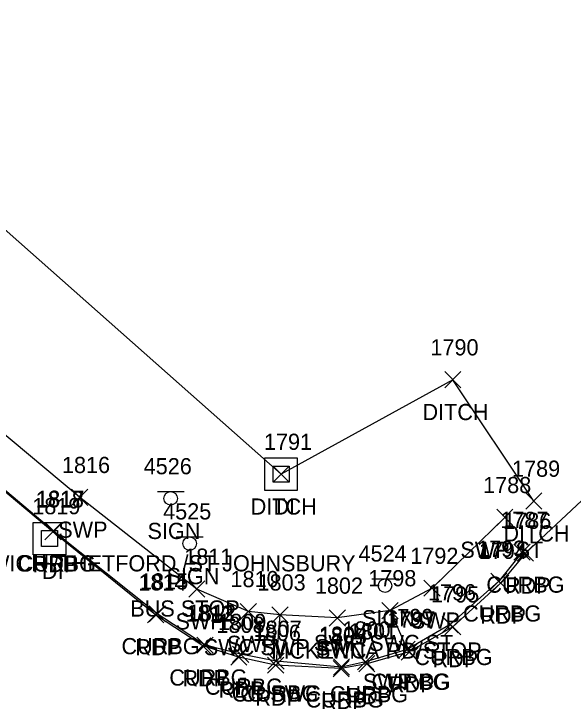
# Model space of a CAD drawing. Extents: x 1690689 to 1696275, y 438760 to 444007.
# Drawn here: x 1691916.7 to 1691985.8, y 439244.2 to 439330.1 of the extents above; entities that cross this region are included whole.
import ezdxf

# ---------------------------------------------------------------- set-up
doc = ezdxf.new("R2010")
doc.units = 0
for name, color, linetype in [('D_A', 7, 'Continuous'), ('D_I', 7, 'Continuous'), ('D_TIC', 7, 'Continuous'), ('DD', 7, 'Continuous'), ('DS', 7, 'Continuous'), ('P_A', 7, 'Continuous'), ('P_I', 7, 'Continuous'), ('P_TIC', 7, 'Continuous'), ('PET', 7, 'Continuous'), ('R_A', 7, 'Continuous'), ('R_I', 7, 'Continuous'), ('R_TIC', 7, 'Continuous'), ('RC', 7, 'Continuous'), ('RSW', 7, 'Continuous'), ('S_A', 7, 'Continuous'), ('S_C', 7, 'Continuous'), ('S_I', 7, 'Continuous'), ('SSGN', 7, 'Continuous')]:
    doc.layers.add(name, color=color, linetype=linetype)

msp = doc.modelspace()

# ---------------------------------------------------------------- linework, layer by layer
at = {"layer": 'D_TIC'}
for points in [[(1691969.983, 439283.898), (1691971.983, 439285.898)], [(1691971.983, 439283.898), (1691969.983, 439285.898)], [(1691948.75, 439272.221), (1691950.75, 439274.221)], [(1691950.75, 439272.221), (1691948.75, 439274.221)], [(1691979.993, 439268.897), (1691981.993, 439270.897)], [(1691981.993, 439268.897), (1691979.993, 439270.897)]]:
    msp.add_lwpolyline(points, dxfattribs=at)
at = {"layer": 'DD'}
msp.add_lwpolyline([(1691980.993, 439269.897), (1691970.983, 439284.898), (1691949.75, 439273.221), (1691908.637, 439309.602), (1691878.878, 439338.951), (1691850.288, 439370.611), (1691847.882, 439389.439)], dxfattribs=at)
at = {"layer": 'DS'}
for p, q in [((1691947.745, 439275.22), (1691951.745, 439275.22)), ((1691947.745, 439271.22), (1691947.745, 439275.22)), ((1691951.745, 439275.22), (1691951.745, 439271.22)), ((1691948.745, 439272.22), (1691948.745, 439274.22)), ((1691948.745, 439274.22), (1691950.745, 439274.22)), ((1691950.745, 439274.22), (1691950.745, 439272.22)), ((1691949.75, 439273.221), (1691949.75, 439273.221)), ((1691949.75, 439273.221), (1691949.75, 439273.221)), ((1691950.745, 439272.22), (1691948.745, 439272.22)), ((1691951.745, 439271.22), (1691947.745, 439271.22)), ((1691919.112, 439267.262), (1691923.112, 439267.262)), ((1691919.112, 439263.262), (1691919.112, 439267.262)), ((1691923.112, 439267.262), (1691923.112, 439263.262)), ((1691920.112, 439264.262), (1691920.112, 439266.262)), ((1691920.112, 439266.262), (1691922.112, 439266.262)), ((1691922.112, 439266.262), (1691922.112, 439264.262)), ((1691921.117, 439265.263), (1691921.117, 439265.263)), ((1691921.117, 439265.263), (1691921.117, 439265.263)), ((1691922.112, 439264.262), (1691920.112, 439264.262)), ((1691923.112, 439263.262), (1691919.112, 439263.262))]:
    msp.add_line(p, q, dxfattribs=at)
at = {"layer": 'P_TIC'}
for points in [[(1691920.536, 439265.097), (1691922.536, 439267.097)], [(1691922.536, 439265.097), (1691920.536, 439267.097)], [(1691978.943, 439262.456), (1691980.943, 439264.456)], [(1691980.943, 439262.456), (1691978.943, 439264.456)], [(1691975.877, 439258.745), (1691977.877, 439260.745)], [(1691977.877, 439258.745), (1691975.877, 439260.745)], [(1691933.231, 439254.841), (1691935.231, 439256.841)], [(1691935.231, 439254.841), (1691933.231, 439256.841)], [(1691969.973, 439253.359), (1691971.973, 439255.359)], [(1691971.973, 439253.359), (1691969.973, 439255.359)], [(1691939.058, 439250.999), (1691941.058, 439252.999)], [(1691941.058, 439250.999), (1691939.058, 439252.999)], [(1691964.575, 439250.247), (1691966.575, 439252.247)], [(1691966.575, 439250.247), (1691964.575, 439252.247)], [(1691943.521, 439249.599), (1691945.521, 439251.599)], [(1691945.521, 439249.599), (1691943.521, 439251.599)], [(1691948.065, 439248.613), (1691950.065, 439250.613)], [(1691950.065, 439248.613), (1691948.065, 439250.613)], [(1691956.174, 439248.184), (1691958.174, 439250.184)], [(1691958.174, 439248.184), (1691956.174, 439250.184)], [(1691959.334, 439248.793), (1691961.334, 439250.793)], [(1691961.334, 439248.793), (1691959.334, 439250.793)]]:
    msp.add_lwpolyline(points, dxfattribs=at)
at = {"layer": 'PET'}
msp.add_lwpolyline([(1691992.617, 439275.273), (1691979.943, 439263.456), (1691976.877, 439259.745), (1691970.973, 439254.359), (1691965.575, 439251.247), (1691960.334, 439249.793), (1691957.174, 439249.184), (1691949.065, 439249.613), (1691944.521, 439250.599), (1691940.058, 439251.999), (1691934.231, 439255.841), (1691921.536, 439266.097), (1691889.347, 439293.069), (1691851.08, 439328.772), (1691838.858, 439341.344)], dxfattribs=at)
at = {"layer": 'R_TIC'}
for points in [[(1691923.832, 439269.357), (1691925.832, 439271.357)], [(1691925.832, 439269.357), (1691923.832, 439271.357)], [(1691976.41, 439266.877), (1691978.41, 439268.877)], [(1691978.41, 439266.877), (1691976.41, 439268.877)], [(1691920.599, 439265.187), (1691922.599, 439267.187)], [(1691922.599, 439265.187), (1691920.599, 439267.187)], [(1691978.534, 439262.57), (1691980.534, 439264.57)], [(1691980.534, 439262.57), (1691978.534, 439264.57)], [(1691975.66, 439259.001), (1691977.66, 439261.001)], [(1691977.66, 439259.001), (1691975.66, 439261.001)], [(1691938.327, 439258.026), (1691940.327, 439260.026)], [(1691940.327, 439258.026), (1691938.327, 439260.026)], [(1691967.406, 439258.126), (1691969.406, 439260.126)], [(1691969.406, 439258.126), (1691967.406, 439260.126)], [(1691933.433, 439254.965), (1691935.433, 439256.965)], [(1691935.433, 439254.965), (1691933.433, 439256.965)], [(1691944.698, 439255.254), (1691946.698, 439257.254)], [(1691946.698, 439255.254), (1691944.698, 439257.254)], [(1691948.598, 439254.837), (1691950.598, 439256.837)], [(1691950.598, 439254.837), (1691948.598, 439256.837)], [(1691948.598, 439254.837), (1691950.598, 439256.837)], [(1691950.598, 439254.837), (1691948.598, 439256.837)], [(1691962.208, 439255.36), (1691964.208, 439257.36)], [(1691964.208, 439255.36), (1691962.208, 439257.36)], [(1691962.208, 439255.36), (1691964.208, 439257.36)], [(1691964.208, 439255.36), (1691962.208, 439257.36)], [(1691955.688, 439254.444), (1691957.688, 439256.444)], [(1691957.688, 439254.444), (1691955.688, 439256.444)], [(1691969.639, 439253.621), (1691971.639, 439255.621)], [(1691971.639, 439253.621), (1691969.639, 439255.621)], [(1691939.345, 439251.087), (1691941.345, 439253.087)], [(1691941.345, 439251.087), (1691939.345, 439253.087)], [(1691964.326, 439250.566), (1691966.326, 439252.566)], [(1691966.326, 439250.566), (1691964.326, 439252.566)], [(1691964.326, 439250.566), (1691966.326, 439252.566)], [(1691966.326, 439250.566), (1691964.326, 439252.566)], [(1691943.741, 439249.958), (1691945.741, 439251.958)], [(1691945.741, 439249.958), (1691943.741, 439251.958)], [(1691948.113, 439249.109), (1691950.113, 439251.109)], [(1691950.113, 439249.109), (1691948.113, 439251.109)], [(1691948.113, 439249.109), (1691950.113, 439251.109)], [(1691950.113, 439249.109), (1691948.113, 439251.109)], [(1691959.189, 439249.026), (1691961.189, 439251.026)], [(1691961.189, 439249.026), (1691959.189, 439251.026)], [(1691956.201, 439248.376), (1691958.201, 439250.376)], [(1691958.201, 439248.376), (1691956.201, 439250.376)]]:
    msp.add_lwpolyline(points, dxfattribs=at)
at = {"layer": 'RC'}
msp.add_lwpolyline([(1691979.534, 439263.57), (1691976.66, 439260.001), (1691970.639, 439254.621), (1691965.326, 439251.566), (1691960.189, 439250.026), (1691957.201, 439249.376), (1691949.113, 439250.109), (1691944.741, 439250.958), (1691940.345, 439252.087), (1691934.433, 439255.965), (1691921.599, 439266.187), (1691889.617, 439293.081), (1691851.246, 439328.908), (1691838.989, 439341.647), (1691832.527, 439350.309), (1691828.967, 439356.68), (1691826.959, 439362.241), (1691824.923, 439373.911), (1691824.475, 439378.625), (1691824.756, 439382.22), (1691826.609, 439391.066), (1691827.708, 439394.808)], dxfattribs=at)
at = {"layer": 'RSW'}
for points in [[(1691949.598, 439255.837), (1691945.698, 439256.254), (1691939.327, 439259.026), (1691924.832, 439270.357), (1691893.022, 439296.931), (1691854.995, 439332.643), (1691842.783, 439345.808), (1691833.662, 439358.89), (1691828.967, 439356.68)], [(1691977.41, 439267.877), (1691968.406, 439259.126), (1691963.208, 439256.36), (1691965.326, 439251.566)], [(1691963.208, 439256.36), (1691956.688, 439255.444), (1691949.598, 439255.837), (1691949.113, 439250.109)]]:
    msp.add_lwpolyline(points, dxfattribs=at)
at = {"layer": 'SSGN'}
for p, q in [((1691934.444, 439271.057), (1691937.777, 439271.057)), ((1691936.09, 439270.224), (1691936.09, 439270.224)), ((1691936.791, 439265.473), (1691940.124, 439265.473)), ((1691938.438, 439264.64), (1691938.438, 439264.64)), ((1691960.947, 439260.272), (1691964.28, 439260.272)), ((1691962.594, 439259.438), (1691962.594, 439259.438))]:
    msp.add_line(p, q, dxfattribs=at)
for centre in [(1691936.09, 439270.224), (1691938.438, 439264.64), (1691962.594, 439259.438)]:
    msp.add_circle(centre, 0.833, dxfattribs=at)

# ---------------------------------------------------------------- texts
at = {"layer": 'D_A'}
for s, p in [('DITCH', (1691967.22, 439279.898)), ('DITCH', (1691945.986, 439268.221)), ('DI', (1691948.805, 439268.221)), ('DITCH', (1691977.229, 439264.897)), ('DI', (1691920.172, 439260.263))]:
    msp.add_text(s, height=2, dxfattribs=at).set_placement(p)
at = {"layer": 'D_I'}
for s, p in [('1790', (1691968.204, 439287.898)), ('1791', (1691947.624, 439276.221)), ('1791', (1691947.624, 439276.221)), ('1789', (1691978.292, 439272.897)), ('1819', (1691918.983, 439268.263))]:
    msp.add_text(s, height=2, dxfattribs=at).set_placement(p)
at = {"layer": 'P_A'}
for p in [(1691919.024, 439261.097), (1691977.432, 439258.456), (1691974.366, 439254.745), (1691931.719, 439250.841), (1691968.462, 439249.359), (1691937.546, 439246.999), (1691963.063, 439246.247), (1691942.009, 439245.599), (1691946.553, 439244.613), (1691957.822, 439244.793), (1691954.663, 439244.184)]:
    msp.add_text('RDP', height=2, dxfattribs=at).set_placement(p)
at = {"layer": 'P_I'}
for s, p in [('1818', (1691919.41, 439269.097)), ('1786', (1691977.195, 439266.456)), ('1794', (1691974.184, 439262.745)), ('1814', (1691932.105, 439258.841)), ('1795', (1691968.281, 439257.359)), ('1813', (1691937.932, 439254.999)), ('1797', (1691962.882, 439254.247)), ('1808', (1691941.749, 439253.599)), ('1806', (1691946.238, 439252.613)), ('1801', (1691958.129, 439252.793)), ('1805', (1691954.403, 439252.184))]:
    msp.add_text(s, height=2, dxfattribs=at).set_placement(p)
at = {"layer": 'R_A'}
for s, p in [('SWP', (1691922.194, 439265.357)), ('SWP ST', (1691971.906, 439262.877)), ('CURBG', (1691917.181, 439261.187)), ('CURBG', (1691975.116, 439258.57)), ('CURBG', (1691972.243, 439255.001)), ('SWP', (1691936.689, 439254.026)), ('SWP', (1691965.768, 439254.126)), ('CURBG', (1691930.016, 439250.965)), ('SWC SWP ST', (1691940.189, 439250.837)), ('SWC SWP ST', (1691940.189, 439250.837)), ('SWP', (1691943.06, 439251.254)), ('SWP SWC ST', (1691953.799, 439251.36)), ('SWP SWC ST', (1691953.799, 439251.36)), ('SWC', (1691954.051, 439250.444)), ('CURBG', (1691966.222, 439249.621)), ('CURBG', (1691935.928, 439247.087)), ('SWP CG', (1691959.853, 439246.566)), ('CURBG', (1691960.908, 439246.566)), ('CURBG', (1691940.324, 439245.958)), ('CG SWC', (1691943.64, 439245.109)), ('CURBG', (1691944.695, 439245.109)), ('CURBG', (1691955.771, 439245.026)), ('CURBG', (1691952.784, 439244.376))]:
    msp.add_text(s, height=2, dxfattribs=at).set_placement(p)
at = {"layer": 'R_I'}
for s, p in [('1816', (1691922.651, 439273.357)), ('1788', (1691974.717, 439270.877)), ('1817', (1691919.473, 439269.187)), ('1787', (1691976.841, 439266.57)), ('1793', (1691973.967, 439263.001)), ('1811', (1691937.768, 439262.026)), ('1792', (1691965.713, 439262.126)), ('1810', (1691943.485, 439259.254)), ('1798', (1691960.515, 439259.36)), ('1798', (1691960.515, 439259.36)), ('1815', (1691932.307, 439258.965)), ('1803', (1691946.827, 439258.837)), ('1803', (1691946.827, 439258.837)), ('1802', (1691953.917, 439258.444)), ('1796', (1691967.891, 439257.621)), ('1812', (1691938.219, 439255.087)), ('1809', (1691941.962, 439253.958)), ('1799', (1691962.625, 439254.566)), ('1799', (1691962.625, 439254.566)), ('1807', (1691946.341, 439253.109)), ('1807', (1691946.341, 439253.109)), ('1804', (1691954.43, 439252.376)), ('1800', (1691957.33, 439253.026))]:
    msp.add_text(s, height=2, dxfattribs=at).set_placement(p)
at = {"layer": 'S_A'}
for p in [(1691933.228, 439265.204), (1691935.576, 439259.619), (1691959.732, 439254.418)]:
    msp.add_text('SIGN', height=2, dxfattribs=at).set_placement(p)
at = {"layer": 'S_C'}
for s, p in [('NORWICH /THETFORD /ST JOHNSBURY', (1691907.693, 439261.204)), ('BUS STOP', (1691931.103, 439255.619)), ('MCKENNA RD/STOP', (1691948.535, 439250.418))]:
    msp.add_text(s, height=2, dxfattribs=at).set_placement(p)
at = {"layer": 'S_I'}
for s, p in [('4526', (1691932.756, 439273.204)), ('4525', (1691935.158, 439267.619)), ('4524', (1691959.314, 439262.418))]:
    msp.add_text(s, height=2, dxfattribs=at).set_placement(p)

doc.saveas('drawing.dxf')
